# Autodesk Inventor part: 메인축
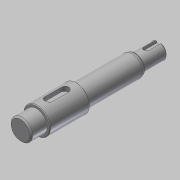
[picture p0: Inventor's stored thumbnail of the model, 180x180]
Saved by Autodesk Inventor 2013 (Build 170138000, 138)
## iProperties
Created: 2019-03
Part Number: 메인축
Material: 강철, 연강
Document SubType Name: Modeling
Designer: mduedu
Density: 1 g/cm^3
Author: mduedu
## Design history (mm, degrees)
sketch "스케치1"
  geometry: L1 (0, 0)-(12, 0); L2 (12, 0)-(12, 8); L3 (12, 8)-(0, 8); L4 (0, 8)-(0, 0); L5 (12, 0)-(42, 0); L6 (42, 0)-(42, 10); L7 (42, 10)-(12, 10); L8 (12, 10)-(12, 0); L9 (42, 0)-(86, 0); L10 (86, 0)-(86, 8); L11 (86, 8)-(42, 8); L12 (42, 8)-(42, 0); L13 (86, 0)-(104, 0); L14 (104, 0)-(104, 6); L15 (104, 6)-(86, 6); L16 (86, 6)-(86, 0)
  constraints: 32 end point, 8 parallel, 4 horizontal, 4 perpendicular
  dimensions: "d0" = 16 diameter of L3 L1; "d2" = 20 diameter of L7 L5; "d3" = 16 diameter of L11 L9; "d4" = 12 diameter of L15 L13; "d5" = 12 distance of L2.end L3.end; "d6" = 30 distance of L6.end L7.end; "d7" = 86 distance between parallel lines of L10 L4; "d8" = 104 distance between parallel lines of L14 L4
revolve "회전1" sketch "스케치1" stored, may be unused: angle "d9" = 90 deg
node "작업 평면1"
sketch "스케치2" dims "d10" = 18
  geometry: L1 (6, -3)-(-6, -3); L2 (-6, -3)-(-6, 3); L3 (-6, 3)-(6, 3); L4 (6, 3)-(6, -3); L5 (15, 10)-(15, -10) reference; 3 further points
  constraints: 8 end point, 2 midpoint, 2 parallel, 2 vertical alignment, 1 horizontal, 1 horizontal alignment, 1 perpendicular, 4 other
  dimensions: "d12" = 6 distance between parallel lines of L3 L1; "d13" = 6 dimension on L5
extrude "돌출1" cut sketch "스케치2" distance "d14" = 3.5; taper "d15" = 0 deg
node "작업 평면2"
sketch "스케치3"
  geometry: L1 (-9, 6)-(-9, -6) reference; L2 (1, -2)-(-9, -2); L3 (1, 2)-(-9, 2); A1 r 2 centre (1, 0) between (1, -2) and (1, 2); 2 further points
  constraints: 4 end point, 2 point on circle, 2 point on line, 2 tangent, 1 centre point, 1 horizontal alignment, 1 midpoint, 1 parallel, 1 perpendicular
  dimensions: "d16" = 12 dimension on A1 L1; "d17" = 4 distance between parallel lines of L3 L2
extrude "돌출2" cut sketch "스케치3" distance "d18" = 2.5; taper "d19" = 0 deg
chamfer "모따기1" distance "d20" = 1; stored, may be unused: second distance "d21" = 2, angle "d22" = 45 deg
chamfer "모따기2" distance "d23" = 0.5; stored, may be unused: second distance "d24" = 2, angle "d25" = 45 deg
chamfer "모따기3" distance "d26" = 1.73; stored, may be unused: second distance "d27" = 2, angle "d28" = 30 deg
fillet "모깎기2" dims "d31" = 0.5, "d32" = 4
node "솔리드1"
